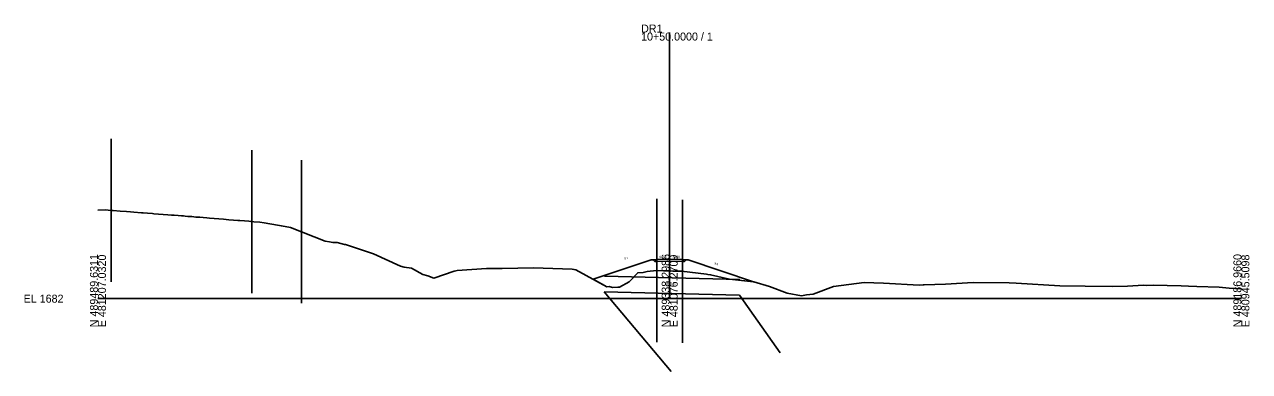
# Model space of a CAD drawing. Extents: x -26 to 403, y -28 to 1060.
# Drawn here: x -25.7 to 402.8, y 474.6 to 595.8 of the extents above; entities that cross this region are included whole.
import ezdxf

# ---------------------------------------------------------------- set-up
doc = ezdxf.new("R2010")
doc.units = 0
for name, color, linetype in [('Exist Cross Section Cell', 7, 'Continuous'), ('Exist XS Center Line Elevation Label', 7, 'Continuous'), ('Exist XS Ground Line', 7, 'Continuous'), ('Prop XS Dump Level', 7, 'Continuous'), ('Prop XS Earthwork Shape', 7, 'Continuous'), ('Prop XS EOT Tick Mark', 7, 'Continuous'), ('Prop XS Finish Grade', 7, 'Continuous'), ('Prop XS Finish Grade Earthwork', 7, 'Continuous'), ('Prop XS Finish Grade Pavement', 7, 'Continuous'), ('Prop XS Pvmt Edge Slope', 7, 'Continuous'), ('Prop XS SE Text', 7, 'Continuous'), ('Prop XS Shoulder Borrow Shape', 7, 'Continuous'), ('Prop XS Side Slope Text', 7, 'Continuous'), ('Prop XS Subgrade Earthwork', 7, 'Continuous'), ('Scratch_Level_4', 7, 'Continuous'), ('Scratch_Level_5', 7, 'Continuous')]:
    doc.layers.add(name, color=color, linetype=linetype)

msp = doc.modelspace()

# ---------------------------------------------------------------- linework, layer by layer
at = {"layer": 'Exist Cross Section Cell'}
for p, q in [((200, 500), (200, 592.98)), ((0, 500), (200, 500)), ((200, 500), (400, 500))]:
    msp.add_line(p, q, dxfattribs=at)
at = {"layer": 'Exist XS Ground Line'}
msp.add_lwpolyline([(0, 530.95), (2.73, 530.99), (3.53, 530.93), (4.48, 530.86), (5.27, 530.79), (7.8, 530.59), (9.96, 530.42), (11.41, 530.3), (12.53, 530.22), (15.23, 530), (15.8, 529.96), (17.32, 529.84), (19.13, 529.7), (19.55, 529.67), (22.87, 529.41), (24.42, 529.3), (25.75, 529.21), (26.68, 529.14), (28.01, 529.04), (29.28, 528.94), (29.95, 528.89), (30.49, 528.85), (31.5, 528.76), (32.36, 528.69), (32.89, 528.65), (34.3, 528.53), (35.63, 528.43), (36.8, 528.34), (38.13, 528.22), (38.97, 528.15), (42.24, 527.89), (43.9, 527.74), (45.79, 527.58), (47.42, 527.46), (48.88, 527.34), (49.23, 527.31), (49.63, 527.28), (51.31, 527.15), (52.8, 527.03), (53.45, 526.97), (54.55, 526.88), (56.61, 526.72), (58.09, 526.47), (62.82, 525.66), (64.16, 525.43), (67.32, 524.92), (79.52, 520.14), (81.06, 519.83), (82.21, 519.68), (83.63, 519.64), (86.26, 518.98), (86.62, 518.87), (96.39, 515.65), (105.85, 511.33), (107.18, 511.02), (109.64, 510.6), (113.6, 508.43), (115.37, 507.98), (117.55, 507.12), (124.65, 509.57), (125.23, 509.78), (125.7, 509.89), (135.88, 510.52), (141.35, 510.59), (152.42, 510.82), (165.87, 510.35), (166.59, 510.18), (167.21, 510.05), (177.99, 504.19), (178.78, 504.28), (180.04, 503.94), (181.86, 504), (182.47, 503.99), (185.78, 505.91), (188.85, 509.03), (190.74, 509.18), (192.17, 509.47), (195.41, 509.84), (195.75, 509.83), (197.8, 509.75), (200, 509.69), (201.16, 509.66), (204.12, 509.62), (212.94, 508.54), (213.4, 508.46), (214.33, 508.36), (220.94, 506.78), (229.46, 505.9), (234.94, 504.28), (241.06, 501.92), (246.09, 501.04), (247.83, 501.28), (250.25, 501.52), (257.33, 504.23), (268.01, 505.65), (274.82, 505.44), (287.23, 504.77), (288.64, 504.84), (289.05, 504.88), (296.51, 505.08), (306.12, 505.64), (318.75, 505.48), (321.24, 505.42), (336.5, 504.5), (345.3, 504.32), (355.07, 504.21), (360.16, 504.37), (365.75, 504.74), (366.73, 504.65), (369.11, 504.68), (378.97, 504.54), (381.49, 504.4), (384.4, 504.3), (392.18, 503.97), (395.67, 503.7), (400, 503.4)], dxfattribs=at)
at = {"layer": 'Prop XS Dump Level'}
for p, q in [((195.5, 513.69), (200, 513.78)), ((200, 513.78), (204.5, 513.69))]:
    msp.add_line(p, q, dxfattribs=at)
at = {"layer": 'Prop XS Earthwork Shape'}
msp.add_lwpolyline([(193.5, 513.53), (173.23, 506.78), (177.99, 504.19), (178.78, 504.28), (180.04, 503.94), (181.86, 504), (182.47, 503.99), (185.78, 505.91), (188.85, 509.03), (190.74, 509.18), (192.17, 509.47), (195.41, 509.84), (195.75, 509.83), (197.8, 509.75), (200, 509.69), (201.16, 509.66), (204.12, 509.62), (212.94, 508.54), (213.4, 508.46), (214.33, 508.36), (220.94, 506.78), (229.37, 505.91), (206.5, 513.53), (205.76, 513.59), (205.18, 513.01), (204.5, 513.03), (200, 513.12), (195.5, 513.03), (194.82, 513.01), (194.24, 513.59)], close=True, dxfattribs=at)
at = {"layer": 'Prop XS EOT Tick Mark'}
for p, q in [((195.5, 513.69), (195.5, 514.69)), ((204.5, 513.69), (204.5, 514.69))]:
    msp.add_line(p, q, dxfattribs=at)
at = {"layer": 'Prop XS Finish Grade'}
for p, q in [((195.5, 513.69), (194.24, 513.59)), ((204.5, 513.69), (205.76, 513.59))]:
    msp.add_line(p, q, dxfattribs=at)
at = {"layer": 'Prop XS Finish Grade Earthwork'}
for p, q in [((193.5, 513.53), (173.23, 506.78)), ((194.24, 513.59), (193.5, 513.53)), ((205.76, 513.59), (206.5, 513.53)), ((206.5, 513.53), (229.37, 505.91))]:
    msp.add_line(p, q, dxfattribs=at)
at = {"layer": 'Prop XS Finish Grade Pavement'}
for p, q in [((195.5, 513.69), (200, 513.78)), ((200, 513.78), (204.5, 513.69))]:
    msp.add_line(p, q, dxfattribs=at)
at = {"layer": 'Prop XS Pvmt Edge Slope'}
for p, q in [((195.5, 513.69), (194.82, 513.01)), ((204.5, 513.69), (205.18, 513.01))]:
    msp.add_line(p, q, dxfattribs=at)
at = {"layer": 'Prop XS Shoulder Borrow Shape'}
for points in [[(195.5, 513.69), (194.24, 513.59), (194.82, 513.01)], [(204.5, 513.69), (205.76, 513.59), (205.18, 513.01)]]:
    msp.add_lwpolyline(points, close=True, dxfattribs=at)
at = {"layer": 'Prop XS Subgrade Earthwork'}
for p, q in [((194.82, 513.01), (194.24, 513.59)), ((195.5, 513.03), (194.82, 513.01)), ((200, 513.12), (195.5, 513.03)), ((204.5, 513.03), (200, 513.12)), ((204.5, 513.03), (205.18, 513.01)), ((205.18, 513.01), (205.76, 513.59))]:
    msp.add_line(p, q, dxfattribs=at)
at = {"layer": 'Scratch_Level_4'}
for p, q in [((4.68, 555.84), (4.68, 505.84)), ((53.82, 551.94), (53.82, 501.94)), ((71.19, 548.4), (71.19, 498.4)), ((195.5, 534.84), (195.5, 484.84)), ((204.5, 534.57), (204.5, 484.57)), ((177.19, 507.85), (224.58, 506.7)), ((177.05, 502.35), (200.48, 474.56)), ((177.05, 502.35), (224.45, 501.2)), ((224.45, 501.2), (238.66, 481.11))]:
    msp.add_line(p, q, dxfattribs=at)
at = {"layer": 'Scratch_Level_5'}
msp.add_lwpolyline([(0, 530.95), (2.73, 530.99), (3.53, 530.93), (4.48, 530.86), (5.27, 530.79), (7.8, 530.59), (9.96, 530.42), (11.41, 530.3), (12.53, 530.22), (15.23, 530), (15.8, 529.96), (17.32, 529.84), (19.13, 529.7), (19.55, 529.67), (22.87, 529.41), (24.42, 529.3), (25.75, 529.21), (26.68, 529.14), (28.01, 529.04), (29.28, 528.94), (29.95, 528.89), (30.49, 528.85), (31.5, 528.76), (32.36, 528.69), (32.89, 528.65), (34.3, 528.53), (35.63, 528.43), (36.8, 528.34), (38.13, 528.22), (38.97, 528.15), (42.24, 527.89), (43.9, 527.74), (45.79, 527.58), (47.42, 527.46), (48.88, 527.34), (49.23, 527.31), (49.63, 527.28), (51.31, 527.15), (52.8, 527.03), (53.45, 526.97), (54.55, 526.88), (56.61, 526.72), (58.09, 526.47), (62.82, 525.66), (64.16, 525.43), (67.32, 524.92), (79.52, 520.14), (81.06, 519.83), (82.21, 519.68), (83.63, 519.64), (86.26, 518.98), (86.62, 518.87), (96.39, 515.65), (105.85, 511.33), (107.18, 511.02), (109.64, 510.6), (113.6, 508.43), (115.37, 507.98), (117.55, 507.12), (124.65, 509.57), (125.23, 509.78), (125.7, 509.89), (135.88, 510.52), (141.35, 510.59), (152.42, 510.82), (165.87, 510.35), (166.59, 510.18), (167.21, 510.05), (177.99, 504.19), (178.78, 504.28), (180.04, 503.94), (181.86, 504), (182.47, 503.99), (185.78, 505.91), (188.85, 509.03), (190.74, 509.18), (192.17, 509.47), (195.41, 509.84), (195.75, 509.83), (197.8, 509.75), (200, 509.69), (201.16, 509.66), (204.12, 509.62), (212.94, 508.54), (213.4, 508.46), (214.33, 508.36), (220.94, 506.78), (229.46, 505.9), (234.94, 504.28), (241.06, 501.92), (246.09, 501.04), (247.83, 501.28), (250.25, 501.52), (257.33, 504.23), (268.01, 505.65), (274.82, 505.44), (287.23, 504.77), (288.64, 504.84), (289.05, 504.88), (296.51, 505.08), (306.12, 505.64), (318.75, 505.48), (321.24, 505.42), (336.5, 504.5), (345.3, 504.32), (355.07, 504.21), (360.16, 504.37), (365.75, 504.74), (366.73, 504.65), (369.11, 504.68), (378.97, 504.54), (381.49, 504.4), (384.4, 504.3), (392.18, 503.97), (395.67, 503.7), (400, 503.4)], dxfattribs=at)

# ---------------------------------------------------------------- texts
at = {"layer": 'Exist Cross Section Cell'}
for s, p in [('DR1', (190, 592.98)), ('10+50.0000 / 1', (190, 590.18)), ('EL 1682', (-26, 498.6))]:
    msp.add_text(s, height=2.8, dxfattribs=at).set_placement(p)
for s, p in [('N 489489.6311', (0, 490)), ('E 481207.0320', (2.8, 490)), ('N 489338.2986', (200, 490)), ('E 481076.2709', (202.8, 490)), ('N 489186.9660', (400, 490)), ('E 480945.5098', (402.8, 490))]:
    msp.add_text(s, height=2.8, rotation=90, dxfattribs=at).set_placement(p)
at = {"layer": 'Exist XS Center Line Elevation Label'}
msp.add_text('1691.69', height=0.75, dxfattribs=at).set_placement((198.45, 504.94))
at = {"layer": 'Prop XS Dump Level'}
for p in [(193.5, 513.49), (206.5, 513.49)]:
    msp.add_text('Case1', height=0.04, dxfattribs=at).set_placement(p)
at = {"layer": 'Prop XS SE Text'}
for rotation, p in [(1.1458, (196.46, 514.21)), (358.8542, (200.96, 514.27))]:
    msp.add_text('0.020', height=0.75, rotation=rotation, dxfattribs=at).set_placement(p)
at = {"layer": 'Prop XS Side Slope Text'}
for rotation, p in [(18.4349, (184.18, 513.51)), (341.5651, (215.55, 512.1))]:
    msp.add_text('3:1', height=0.75, rotation=rotation, dxfattribs=at).set_placement(p)

doc.saveas('drawing.dxf')
